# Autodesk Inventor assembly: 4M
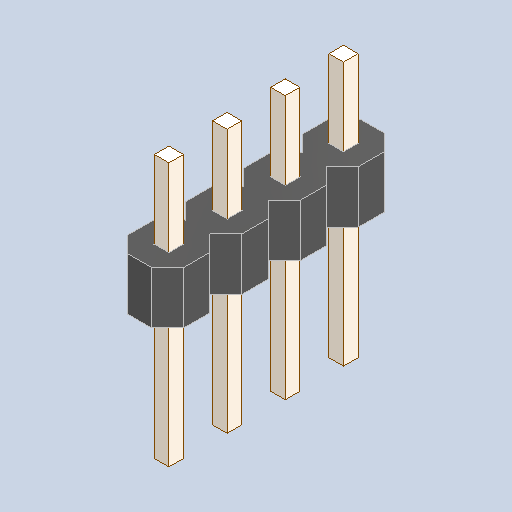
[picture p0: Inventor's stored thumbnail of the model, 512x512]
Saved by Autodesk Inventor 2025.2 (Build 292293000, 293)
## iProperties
Created: 2025-04
Part Number: 4M
Description: PART--DESC
Document SubType Name: Assembly
Designer: BennF
Author: BennF
Revision Number: NONE
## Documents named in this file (3)
- C:\Users\BennF\Nextcloud\Benutzer\CNC JarBeRi\existing parts\Electronics\RepRap A4988 Shied (USE WITHOUT ARDUINO)\reprap-a4988-1.snapshot.1\RepRap\RepRap\4M_1.iam
- C:\Users\BennF\Nextcloud\Benutzer\CNC JarBeRi\existing parts\Electronics\RepRap A4988 Shied (USE WITHOUT ARDUINO)\reprap-a4988-1.snapshot.1\RepRap\RepRap\4M Geometry.ipt
- C:\Users\BennF\Nextcloud\Benutzer\CNC JarBeRi\existing parts\Electronics\RepRap A4988 Shied (USE WITHOUT ARDUINO)\reprap-a4988-1.snapshot.1\RepRap\RepRap\Pin5.ipt
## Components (2 placed, 2 different names)
1. 4M Geometry
2. Pin5
